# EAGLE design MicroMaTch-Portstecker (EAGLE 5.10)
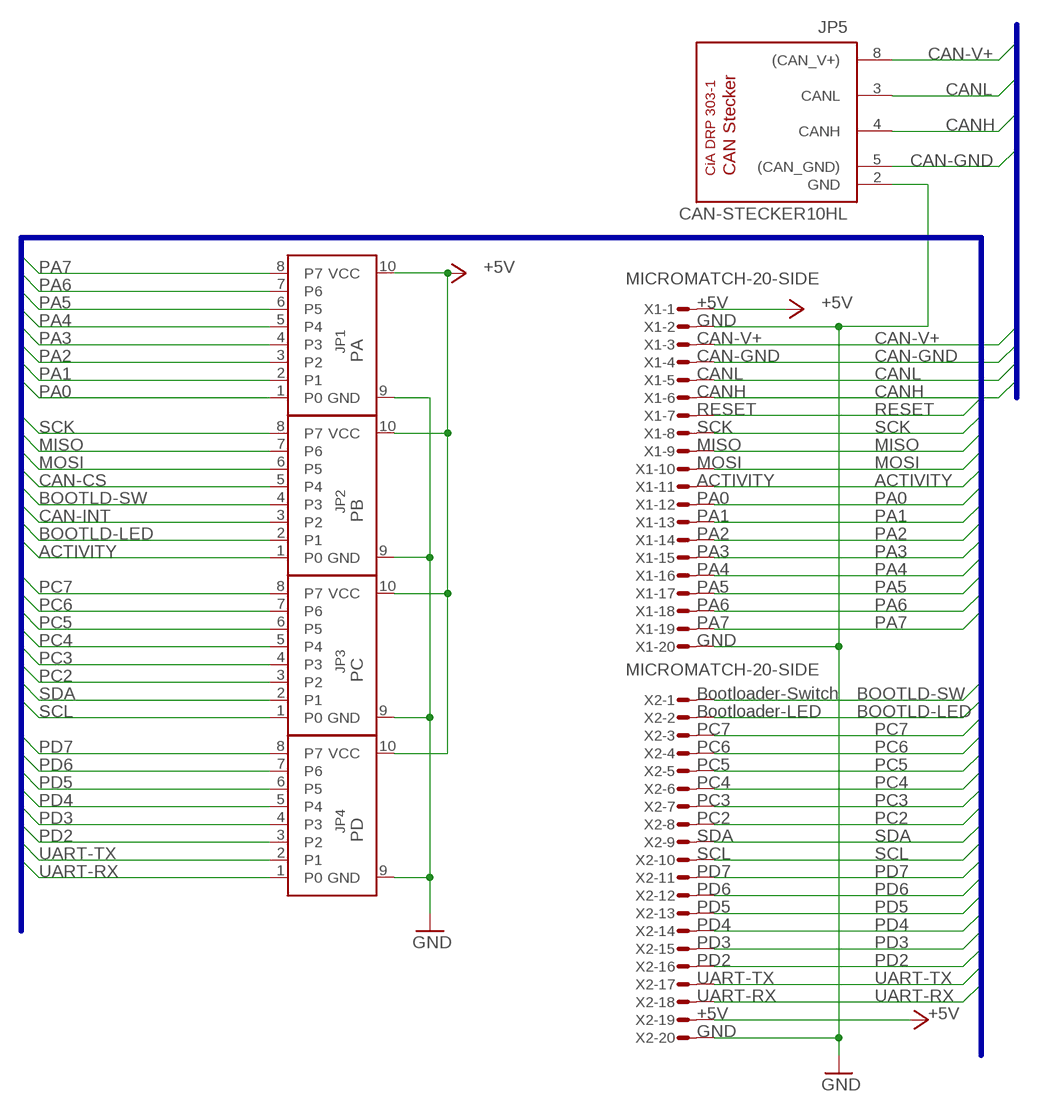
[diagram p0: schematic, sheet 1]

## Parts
JP1  PA  AVR_PORTL  [WINKELWANNE_ML10L]
JP2  PB  AVR_PORTL  [WINKELWANNE_ML10L]
JP3  PC  AVR_PORTL  [WINKELWANNE_ML10L]
JP4  PD  AVR_PORTL  [WINKELWANNE_ML10L]
JP5  CAN-STECKER10HL  [WINKELWANNE_ML10L]
X1  MICROMATCH-20-SIDE  [MICROMATCH-20-SIDE]
X2  MICROMATCH-20-SIDE  [MICROMATCH-20-SIDE]

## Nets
+5V: JP1.10(VCC) JP2.10(VCC) JP3.10(VCC) JP4.10(VCC) X1.1 X2.19
ACTIVITY: JP2.1(P0) X1.11
BOOTLD-LED: JP2.2(P1) X2.2
BOOTLD-SW: JP2.4(P3) X2.1
CAN-CS: JP2.5(P4)
CAN-GND [Power]: JP5.5((CAN_GND)) X1.4
CAN-INT: JP2.3(P2)
CAN-V+ [Power]: JP5.8((CAN_V+)) X1.3
CANH: JP5.4(CANH) X1.6
CANL: JP5.3(CANL) X1.5
GND: JP1.9(GND) JP2.9(GND) JP3.9(GND) JP4.9(GND) JP5.2(GND) X1.2 X1.20 X2.20
MISO: JP2.7(P6) X1.9
MOSI: JP2.6(P5) X1.10
PA0: JP1.1(P0) X1.12
PA1: JP1.2(P1) X1.13
PA2: JP1.3(P2) X1.14
PA3: JP1.4(P3) X1.15
PA4: JP1.5(P4) X1.16
PA5: JP1.6(P5) X1.17
PA6: JP1.7(P6) X1.18
PA7: JP1.8(P7) X1.19
PC2: JP3.3(P2) X2.8
PC3: JP3.4(P3) X2.7
PC4: JP3.5(P4) X2.6
PC5: JP3.6(P5) X2.5
PC6: JP3.7(P6) X2.4
PC7: JP3.8(P7) X2.3
PD2: JP4.3(P2) X2.16
PD3: JP4.4(P3) X2.15
PD4: JP4.5(P4) X2.14
PD5: JP4.6(P5) X2.13
PD6: JP4.7(P6) X2.12
PD7: JP4.8(P7) X2.11
RESET: X1.7
SCK: JP2.8(P7) X1.8
SCL: JP3.1(P0) X2.10
SDA: JP3.2(P1) X2.9
UART-RX: JP4.1(P0) X2.18
UART-TX: JP4.2(P1) X2.17

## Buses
PA[0..7],PC[2..7],PD[2..7],SCK,MISO,MOSI,CAN-CS,BOOTLD-SW,CAN-INT,BOOTLD-LED,ACTIVITY,SDA,SCL,UART-RX,UART-TX,CLK,RESET
CANL,CANH,CAN-V+,CAN-GND

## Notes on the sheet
- +5V
- GND
- CAN-V+
- CAN-GND
- CANL
- CANH
- RESET
- SCK
- MISO
- MOSI
- ACTIVITY
- PA0
- PA1
- PA2
- PA3
- PA4
- PA5
- PA6
- PA7
- GND
- Bootloader-Switch
- Bootloader-LED
- PC7
- PC6
- PC5
- PC4
- PC3
- PC2
- SDA
- SCL
- PD7
- PD6
- PD5
- PD4
- PD3
- PD2
- UART-TX
- UART-RX
- +5V
- GND

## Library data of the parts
JP1-JP4 = 11my-AVR:AVR_PORT: Datenportstecker Kompatibel zu den Steckern des STK500
JP5 = 11my-CAN:CAN-STECKER: CAN Stecker nach CiA DRP 303-1
X1 X2 = apbteam_con-amp-micromatch:MICROMATCH-20: Micro-MaTch 20 Straight connector: Suited for both, female and male.

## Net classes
0 default: width 0.15 mm, clearance 0.25 mm
1 Power: width 0.5 mm, clearance 0.25 mm

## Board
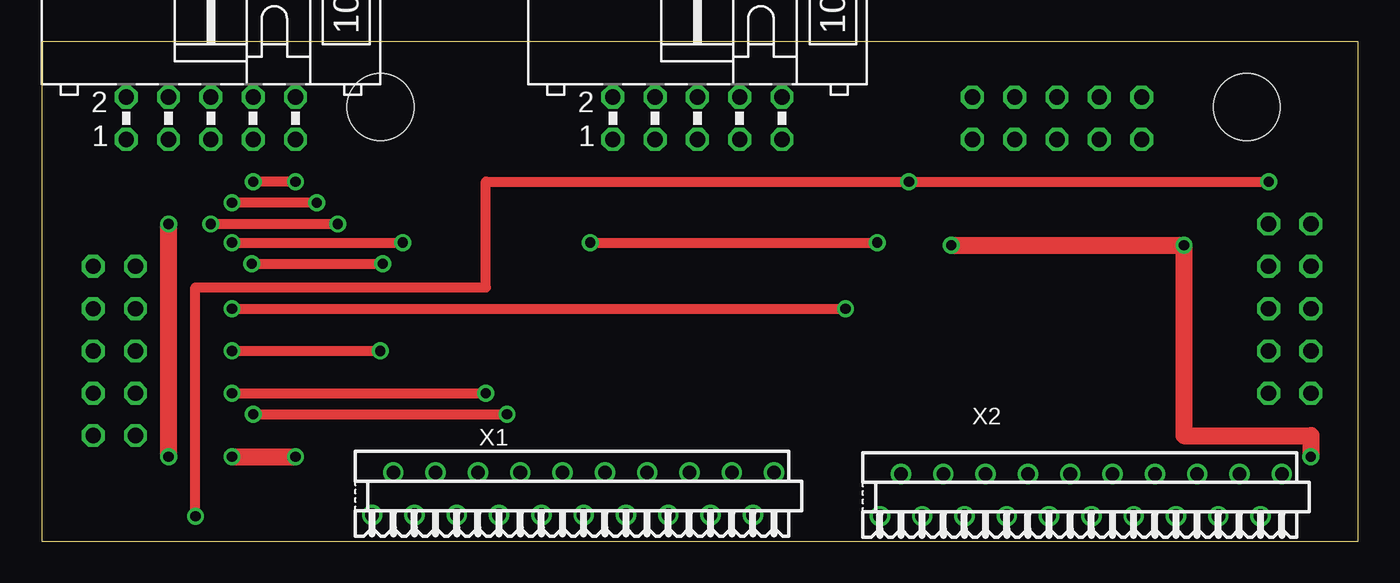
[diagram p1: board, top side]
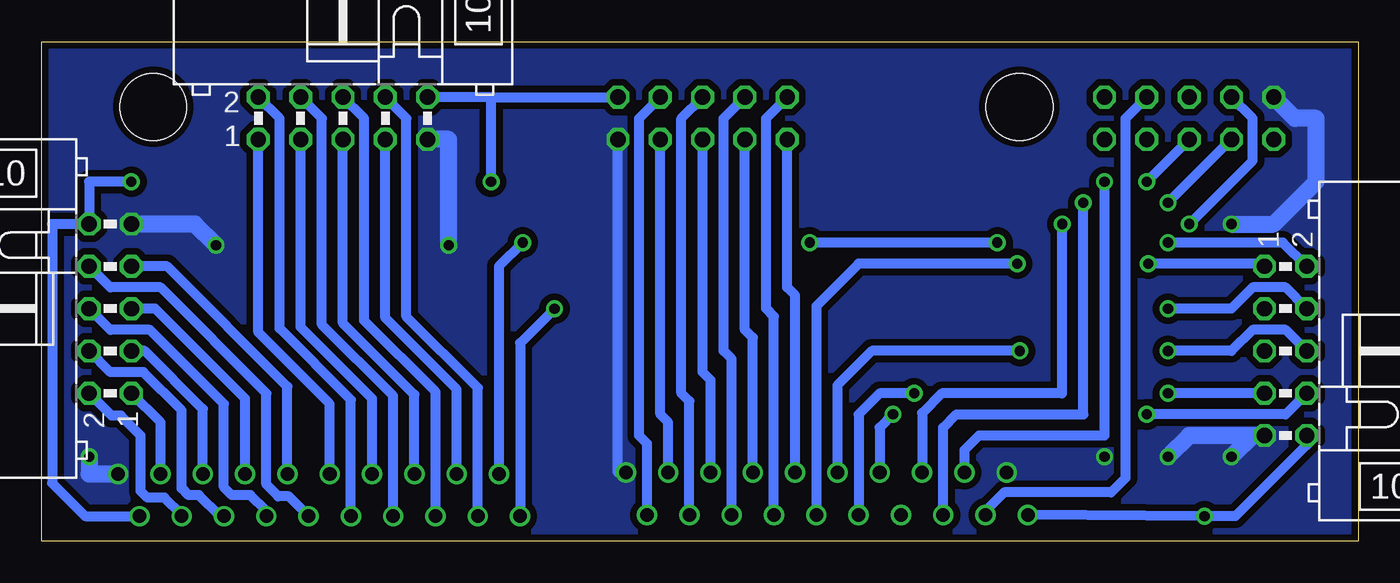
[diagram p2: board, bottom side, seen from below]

Size 79.05 x 30 mm. Coordinates in mm from the lower left corner, seen from the top.
Outline: 0,0 79.05,0 79.05,30 0,30 0,0
Copper layers (1+2*15+16): Top 0.035mm / dielectric 0.36mm / layer 2 0.018mm / dielectric 0.71mm / layer 15 0.018mm / dielectric 0.36mm / Bottom 0.035mm
Design rules "q-print.info *": minimum track width 6mil, minimum drill 0.3mm, track to track 10mil, track to pad 10mil, pad to pad 10mil, via to via 10mil, smd to smd 10mil, copper to edge 0.3mm, drill to drill 10mil, minimum pad ring 8mil, minimum via ring 8mil, stop-mask expansion 4mil, vias tented up to drill 16mil, thermal gap 10mil
Holes 4 mm at 20.35,26.08 72.35,26.08

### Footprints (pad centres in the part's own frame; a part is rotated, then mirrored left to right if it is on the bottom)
WINKELWANNE_ML10L = drill 0.914 octagon: 1 -5.08,-1.27; 2 -5.08,1.27; 3 -2.54,-1.27; 4 -2.54,1.27; 5 0,-1.27; 6 0,1.27; 7 2.54,-1.27; 8 2.54,1.27; 9 5.08,-1.27; 10 5.08,1.27
MICROMATCH-20-SIDE = drill 0.813 round: 1 12.065,1.27; 2 10.795,-1.27; 3 9.525,1.27; 4 8.255,-1.27; 5 6.985,1.27; 6 5.715,-1.27; 7 4.445,1.27; 8 3.175,-1.27; 9 1.905,1.27; 10 0.635,-1.27; 11 -0.635,1.27; 12 -1.905,-1.27; 13 -3.175,1.27; 14 -4.445,-1.27; 15 -5.715,1.27; 16 -6.985,-1.27; 17 -8.255,1.27; 18 -9.525,-1.27; 19 -10.795,1.27; 20 -12.065,-1.27

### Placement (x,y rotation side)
JP1  39.37,25.4 0 top
JP2  4.37,11.43 270 bottom
JP3  60.96,25.4 0 bottom
JP4  74.93,13.97 90 bottom
JP5  10.16,25.4 0 top
X1  31.91,2.86 180 top
X2  62.39,2.78 180 top

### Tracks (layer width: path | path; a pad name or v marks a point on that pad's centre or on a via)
+5V  (via drill 0.61)
  Top 0.61: v73.66,21.59 v52.07,21.59 26.67,21.59 26.67,15.24 9.23,15.24 v9.23,1.51
  Bottom 0.61: JP2.10 3.1,5.79 7.38,1.51 v9.23,1.51 X1.1 | v73.66,21.59 76.2,21.59 JP4.10 78.42,19.05 78.42,3.49 76.44,1.51 X2.19 | v52.07,21.59 52.07,26.67 | 52.07,26.67 JP3.10 | 52.07,26.67 JP1.10
ACTIVITY  (via drill 0.61)
  Top 0.61: v12.62,16.67 v20.48,16.67
  Bottom 0.61: v20.48,16.67 30,16.67 32.54,14.13 X1.11 | v12.62,16.67 5.79,16.67 JP2.1
BOOTLD-LED  (via drill 0.61)
  Top 0.61: v11.43,17.94 v21.67,17.94 | v32.94,17.94 v50.16,17.94
  Bottom 0.61: v21.67,17.94 v32.94,17.94 | v11.43,17.94 4.52,17.94 JP2.2 | v50.16,17.94 51.59,16.51 X2.2
BOOTLD-SW  (via drill 0.61)
  Top 0.61: v11.43,13.97 v48.26,13.97
  Bottom 0.61: v11.43,13.97 7.62,13.97 6.35,15.24 4.37,15.24 JP2.4 | v48.26,13.97 50.32,11.91 X2.1
CAN-GND  (via drill 0.61)
  Top 0.61: v15.24,21.59 v12.7,21.59
  Bottom 0.61: v12.7,21.59 JP5.5 | v15.24,21.59 15.24,6.35 22.78,6.35 23.65,5.48 X1.4
CAN-V+
  Bottom 0.61: JP5.8 13.97,25.4 13.97,3.81 14.84,2.94 21.27,2.94 22.38,1.83 X1.3
CANH  (via drill 0.61)
  Top 0.61: v17.78,19.05 v10.16,19.05
  Bottom 0.61: v10.16,19.05 6.35,22.86 6.35,25.4 JP5.4 | v17.78,19.05 17.78,8.89 25,8.89 26.19,7.7 X1.6
CANL  (via drill 0.61)
  Top 0.61: v16.51,20.32 v11.43,20.32
  Bottom 0.61: v16.51,20.32 16.51,7.62 24.13,7.62 24.92,6.83 X1.5 | v11.43,20.32 JP5.3
GND  (via drill 0.61)
  Top 1.016: v54.61,17.78 v68.58,17.78 68.58,6.35 76.2,6.35 v76.2,5.08 | v11.43,5.08 v15.24,5.08 | v7.62,5.08 v7.62,19.05
  Bottom 0.61: JP1.9 44.45,4.13 X1.20
  Bottom 1.016: JP3.9 54.61,24.13 v54.61,17.78 | v68.58,17.78 69.85,19.05 JP4.9 | v11.43,5.08 10.16,6.35 JP2.9 6.35,6.35 v7.62,5.08 | JP5.2 3.81,25.4 2.54,25.4 2.54,21.59 5.08,19.05 v7.62,19.05 | v76.2,5.08 76.2,4.05 X2.20
  pour Bottom (isolate 0.4, rank 3, no thermals): 0,0 79.05,0 79.05,30 0,30
MISO  (via drill 0.61)
  Top 0.61: v11.43,8.89 v26.67,8.89
  Bottom 0.61: JP2.7 v11.43,8.89 | v26.67,8.89 28.73,8.89 30,7.62 X1.9
MOSI  (via drill 0.61)
  Top 0.61: v11.43,11.43 v20.32,11.43
  Bottom 0.61: v20.32,11.43 29.21,11.43 31.27,9.37 X1.10 | v11.43,11.43 7.62,11.43 6.35,12.7 4.37,12.7 JP2.6
PA0
  Bottom 0.61: JP1.1 34.29,15.24 33.81,14.76 X1.12
PA1
  Bottom 0.61: JP1.2 35.56,25.4 35.56,13.97 35.08,13.49 X1.13
PA2
  Bottom 0.61: JP1.3 36.83,12.7 36.35,12.22 X1.14
PA3
  Bottom 0.61: JP1.4 38.1,25.4 38.1,11.43 37.62,10.95 X1.15
PA4
  Bottom 0.61: JP1.5 39.37,10.16 38.89,9.68 X1.16
PA5
  Bottom 0.61: JP1.6 40.64,25.4 40.64,8.89 40.16,8.41 X1.17
PA6
  Bottom 0.61: JP1.7 41.91,7.62 41.43,7.14 X1.18
PA7
  Bottom 0.61: JP1.8 43.18,25.4 43.18,6.35 42.7,5.87 X1.19
PC2
  Bottom 0.61: JP3.3 63.5,12.86 59.21,8.57 X2.8
PC3
  Bottom 0.61: JP3.4 62.23,25.4 62.23,13.02 57.94,8.73 X2.7
PC4
  Bottom 0.61: JP3.5 60.96,13.1 56.67,8.81 X2.6
PC5
  Bottom 0.61: JP3.6 59.69,25.4 59.69,13.26 55.4,8.97 X2.5
PC6
  Bottom 0.61: JP3.7 58.42,13.41 54.13,9.13 X2.4
PC7
  Bottom 0.61: JP3.8 57.15,25.4 57.15,13.49 52.86,9.21 X2.3
PD2
  Bottom 0.61: JP4.3 72.87,11.43 69.37,7.94 X2.16
PD3
  Bottom 0.61: JP4.4 74.93,10.16 72.95,10.16 70.64,7.86 70.64,3.17 70.25,2.78 69.61,2.78 68.34,1.51 X2.15
PD4
  Bottom 0.61: JP4.5 72.23,13.97 66.83,8.57 X2.14
PD5
  Bottom 0.61: JP4.6 74.93,12.7 72.55,12.7 68.1,8.26 68.1,3.25 67.63,2.78 66.52,2.78 65.56,1.83 X2.13
PD6
  Bottom 0.61: JP4.7 71.52,16.51 64.29,9.29 X2.12
PD7
  Bottom 0.61: JP4.8 74.93,15.24 71.91,15.24 65.56,8.89 65.56,3.41 64.85,2.7 64.21,2.7 X2.11 | X2.11
SCK  (via drill 0.61)
  Top 0.61: v12.7,7.62 v27.94,7.62
  Bottom 0.61: JP2.8 4.37,7.62 v12.7,7.62 | v27.94,7.62 28.73,6.83 X1.8
SCL
  Bottom 0.61: JP3.1 66.04,12.54 61.75,8.26 X2.10
SDA
  Bottom 0.61: JP3.2 64.77,25.4 64.77,12.78 60.48,8.49 X2.9
UART-RX
  Bottom 0.61: X2.18 71.91,7.14 JP4.1
UART-TX
  Bottom 0.61: JP4.2 74.85,7.54 74.3,7.54 73.1,6.35 73.1,3.02 72.71,2.62 71.68,2.62 70.64,1.59 X2.17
